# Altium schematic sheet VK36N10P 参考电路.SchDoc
size A4
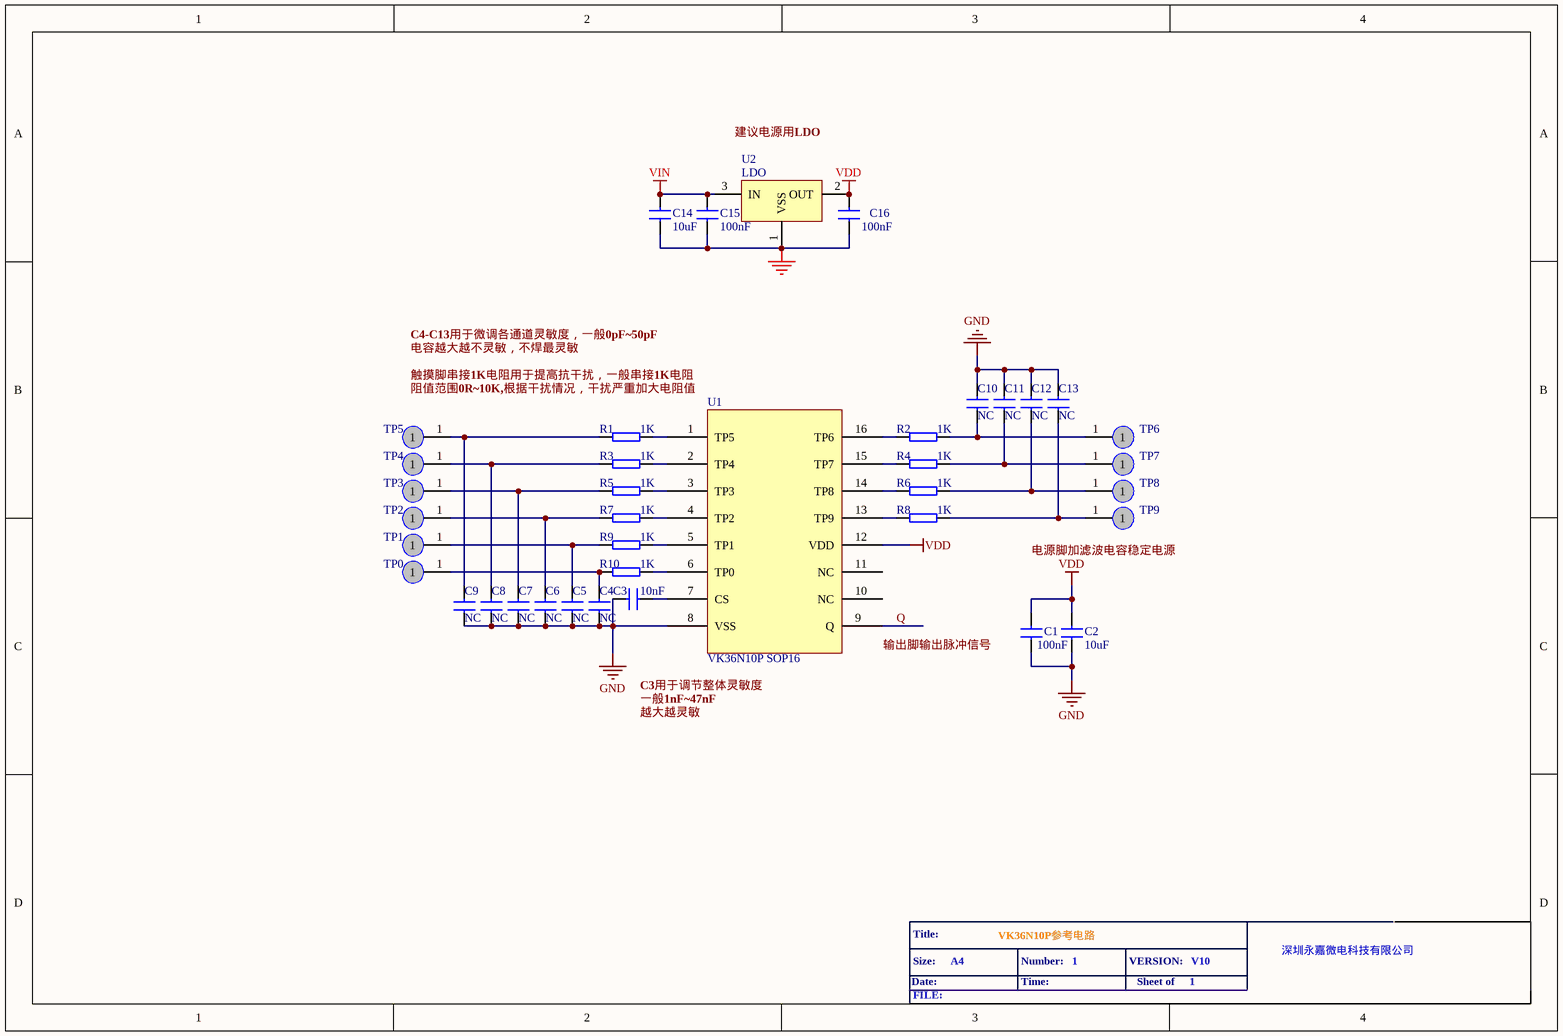
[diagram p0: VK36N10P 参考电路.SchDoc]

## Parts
C1  100nF  [0603-C]
C2  10uF  [0603-C]
C3  value 10nF  [0603-C]  (hidden comment: 10uF)
C4  value NC  [0603-C]  (hidden comment: 10uF)
C5  value NC  [0603-C]  (hidden comment: 10uF)
C6  value NC  [0603-C]  (hidden comment: 10uF)
C7  value NC  [0603-C]  (hidden comment: 10uF)
C8  value NC  [0603-C]  (hidden comment: 10uF)
C9  value NC  [0603-C]  (hidden comment: 10uF)
C10  value NC  [0603-C]  (hidden comment: 10uF)
C11  value NC  [0603-C]  (hidden comment: 10uF)
C12  value NC  [0603-C]  (hidden comment: 10uF)
C13  value NC  [0603-C]  (hidden comment: 10uF)
C14  10uF  [0805-C]
C15  100nF  [0805-C]
C16  100nF  [0805-C]
R1  1K  [0603-R]
R2  1K  [0603-R]
R3  1K  [0603-R]
R4  1K  [0603-R]
R5  1K  [0603-R]
R6  1K  [0603-R]
R7  1K  [0603-R]
R8  1K  [0603-R]
R9  1K  [0603-R]
R10  1K  [0603-R]
TP0  TPAD  [TP-PAD0]  (value not drawn)
TP1  TPAD  [TP-PAD0]  (value not drawn)
TP2  TPAD  [TP-PAD0]  (value not drawn)
TP3  TPAD  [TP-PAD0]  (value not drawn)
TP4  TPAD  [TP-PAD0]  (value not drawn)
TP5  TPAD  [TP-PAD0]  (value not drawn)
TP6  TPAD  [TP-PAD0]  (value not drawn)
TP7  TPAD  [TP-PAD0]  (value not drawn)
TP8  TPAD  [TP-PAD0]  (value not drawn)
TP9  TPAD  [TP-PAD0]  (value not drawn)
U1  VK36N10P SOP16
U2  LDO  [SOT-23]

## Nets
GND: C1.2 C2.2 C3.2 C4.1 C5.1 C6.1 C7.1 C8.1 C9.1 C10.2 C11.2 C12.2 C13.2 C14.2 C15.2 C16.2 U1.8(VSS) U2.1(VSS)
VDD: C1.1 C2.1 C16.1 U1.12(VDD) U2.2(OUT)
VIN: C14.1 C15.1 U2.3(IN)
Q: U1.9(Q)
NetC3_1: C3.1 U1.7(CS)
NetC4_2: C4.2 R10.2 TP0.1
NetC5_2: C5.2 R9.2 TP1.1
NetC6_2: C6.2 R7.2 TP2.1
NetC7_2: C7.2 R5.2 TP3.1
NetC8_2: C8.2 R3.2 TP4.1
NetC9_2: C9.2 R1.2 TP5.1
NetC10_1: C10.1 R2.2 TP6.1
NetC11_1: C11.1 R4.2 TP7.1
NetC12_1: C12.1 R6.2 TP8.1
NetC13_1: C13.1 R8.2 TP9.1
NetR1_1: R1.1 U1.1(TP5)
NetR2_1: R2.1 U1.16(TP6)
NetR3_1: R3.1 U1.2(TP4)
NetR4_1: R4.1 U1.15(TP7)
NetR5_1: R5.1 U1.3(TP3)
NetR6_1: R6.1 U1.14(TP8)
NetR7_1: R7.1 U1.4(TP2)
NetR8_1: R8.1 U1.13(TP9)
NetR9_1: R9.1 U1.5(TP1)
NetR10_1: R10.1 U1.6(TP0)

Not connected (* = marked no-connect by the designer): U1 10(NC) 11(NC)

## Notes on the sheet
- 建议电源用LDO
- 触摸脚串接1K电阻用于提高抗干扰，一般串接1K电阻
- C4-C13用于微调各通道灵敏度，一般0pF~50pF
- 电容越大越不灵敏，不焊最灵敏
- 阻值范围0R
  0K,根据干扰情况，干扰严重加大电阻值
- (near TP9) 电源脚加滤波电容稳定电源
- (near U1) 输出脚输出脉冲信号
- C3用于调节整体灵敏度
- 一般1nF~47nF
- 越大越灵敏
- Date:
- Title:
- Size:
- A4
- VK36N10P参考电路
- Number:
- Time:
- 1
- VERSION:
- Sheet of
- V10
- 深圳永嘉微电科技有限公司
- FILE:

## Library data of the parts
C1-C16 = CAP: Capacitor
R1-R10 = RES: Resistor
TP0-TP9 = TPAD: TESTING
U1 = VK36N10PI SOP16
U2 = V6206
